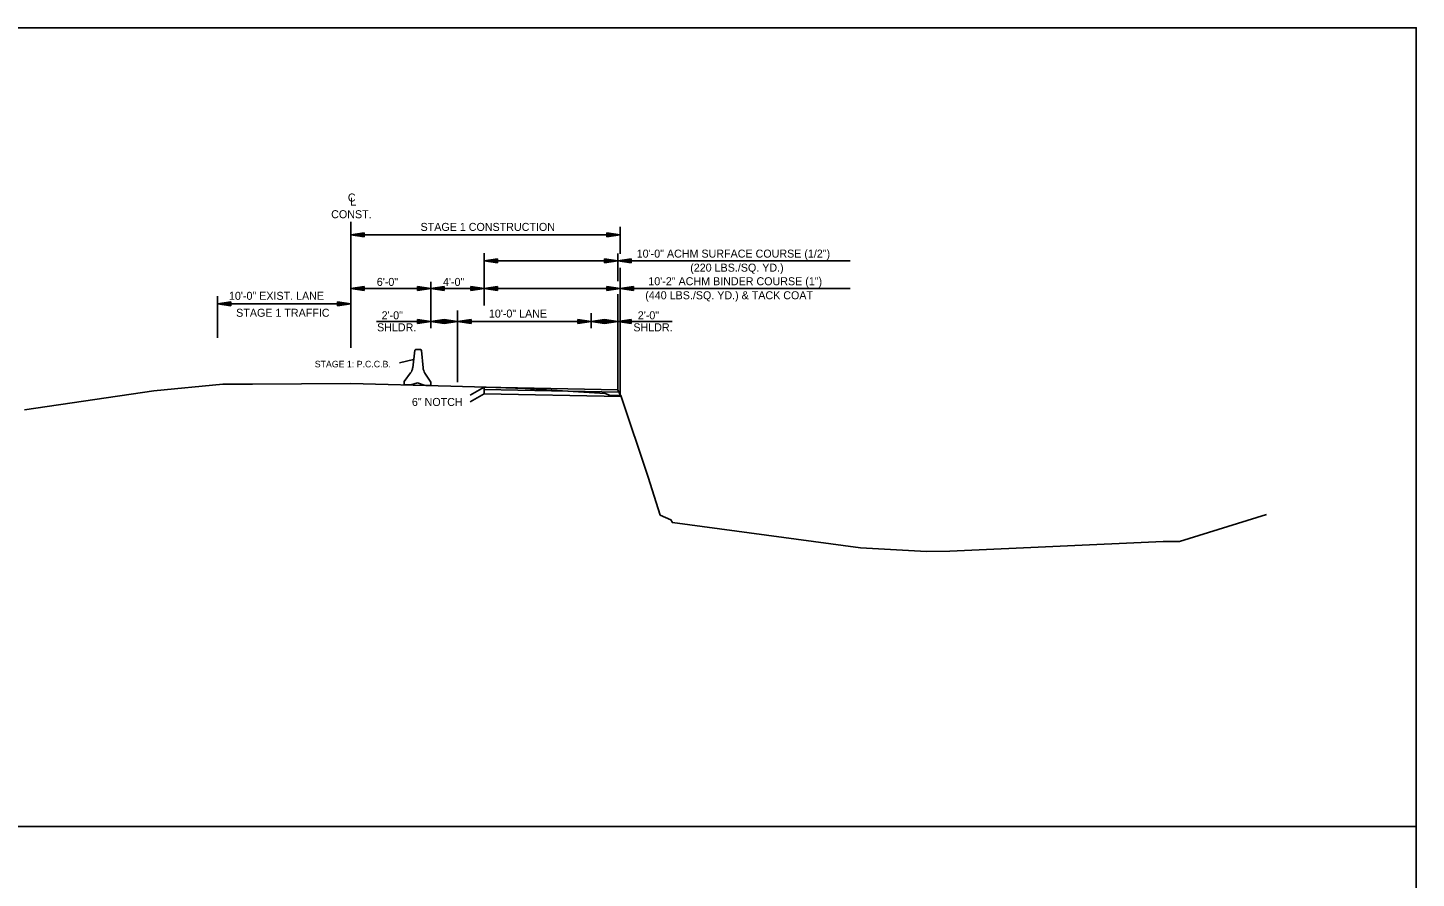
# Model space of a CAD drawing. Extents: x 2829243 to 2838161, y 467639 to 474695.
# Drawn here: x 2830081 to 2831122, y 469629 to 470266 of the extents above; entities that cross this region are included whole.
import ezdxf

# ---------------------------------------------------------------- set-up
doc = ezdxf.new("R2010")
doc.units = 0
for name, color, linetype in [('Default', 7, 'Continuous'), ('R_Dimension', 7, 'Continuous'), ('R_Draft', 7, 'Continuous'), ('R_Exist Surface', 7, 'Continuous'), ('R_Fin Surface', 7, 'Continuous'), ('R_MOT', 7, 'Continuous')]:
    doc.layers.add(name, color=color, linetype=linetype)

msp = doc.modelspace()

# ---------------------------------------------------------------- linework, layer by layer
at = {"layer": 'Default'}
msp.add_line((2829486.2, 469667.7), (2831121.8, 469667.7), dxfattribs=at)
msp.add_lwpolyline([(2829486.2, 470265.9), (2831121.8, 470265.9), (2831121.8, 468471.1), (2829486.2, 468471.1)], close=True, dxfattribs=at)
at = {"layer": 'R_Dimension'}
for p, q in [((2830323.3, 470026.2), (2830323.3, 470120.7)), ((2830333.3, 470112.3), (2830323.3, 470110.8)), ((2830323.3, 470110.8), (2830525.1, 470110.8)), ((2830333.3, 470109.3), (2830323.3, 470110.8)), ((2830333.3, 470112), (2830325, 470110.8)), ((2830333.3, 470109.5), (2830325, 470110.8)), ((2830333.3, 470111.8), (2830326.7, 470110.8)), ((2830333.3, 470109.8), (2830326.7, 470110.8)), ((2830333.3, 470111.5), (2830328.4, 470110.8)), ((2830333.3, 470110), (2830328.4, 470110.8)), ((2830333.3, 470111.3), (2830330.1, 470110.8)), ((2830333.3, 470110.3), (2830330.1, 470110.8)), ((2830333.3, 470111), (2830331.8, 470110.8)), ((2830333.3, 470110.5), (2830331.8, 470110.8)), ((2830333.3, 470109.3), (2830333.3, 470112.3)), ((2830515.1, 470112.3), (2830525.1, 470110.8)), ((2830515.1, 470109.3), (2830515.1, 470112.3)), ((2830515.1, 470112), (2830523.4, 470110.8)), ((2830515.1, 470111.8), (2830521.7, 470110.8)), ((2830515.1, 470111.5), (2830520, 470110.8)), ((2830515.1, 470111.3), (2830518.3, 470110.8)), ((2830515.1, 470111), (2830516.6, 470110.8)), ((2830515.1, 470109.3), (2830525.1, 470110.8)), ((2830515.1, 470110.3), (2830518.3, 470110.8)), ((2830515.1, 470109.8), (2830521.7, 470110.8)), ((2830515.1, 470109.5), (2830523.4, 470110.8)), ((2830515.1, 470110), (2830520, 470110.8)), ((2830515.1, 470110.5), (2830516.6, 470110.8)), ((2830525.1, 470096.6), (2830525.1, 470116.8)), ((2830423.3, 470058), (2830423.3, 470097.2)), ((2830433.3, 470092.9), (2830423.3, 470091.4)), ((2830423.3, 470091.4), (2830697.7, 470091.4)), ((2830433.3, 470089.9), (2830423.3, 470091.4)), ((2830433.3, 470092.6), (2830425, 470091.4)), ((2830433.3, 470090.1), (2830425, 470091.4)), ((2830433.3, 470092.4), (2830426.7, 470091.4)), ((2830433.3, 470090.4), (2830426.7, 470091.4)), ((2830433.3, 470092.1), (2830428.4, 470091.4)), ((2830433.3, 470090.6), (2830428.4, 470091.4)), ((2830433.3, 470091.9), (2830430.1, 470091.4)), ((2830433.3, 470090.9), (2830430.1, 470091.4)), ((2830433.3, 470091.6), (2830431.8, 470091.4)), ((2830433.3, 470091.1), (2830431.8, 470091.4)), ((2830433.3, 470089.9), (2830433.3, 470092.9)), ((2830513.4, 470092.9), (2830523.4, 470091.4)), ((2830513.4, 470089.9), (2830513.4, 470092.9)), ((2830513.4, 470092.6), (2830521.7, 470091.4)), ((2830513.4, 470092.4), (2830520, 470091.4)), ((2830513.4, 470092.1), (2830518.3, 470091.4)), ((2830513.4, 470091.9), (2830516.6, 470091.4)), ((2830513.4, 470091.6), (2830515, 470091.4)), ((2830513.4, 470089.9), (2830523.4, 470091.4)), ((2830513.4, 470090.9), (2830516.6, 470091.4)), ((2830513.4, 470090.4), (2830520, 470091.4)), ((2830513.4, 470090.1), (2830521.7, 470091.4)), ((2830513.4, 470090.6), (2830518.3, 470091.4)), ((2830513.4, 470091.1), (2830515, 470091.4)), ((2830523.4, 470076.2), (2830523.4, 470096.8)), ((2830533.4, 470092.9), (2830523.4, 470091.4)), ((2830533.4, 470089.9), (2830523.4, 470091.4)), ((2830533.4, 470092.6), (2830525.1, 470091.4)), ((2830533.4, 470090.1), (2830525.1, 470091.4)), ((2830533.4, 470092.4), (2830526.8, 470091.4)), ((2830533.4, 470090.4), (2830526.8, 470091.4)), ((2830533.4, 470092.1), (2830528.4, 470091.4)), ((2830533.4, 470090.6), (2830528.4, 470091.4)), ((2830533.4, 470091.9), (2830530.1, 470091.4)), ((2830533.4, 470090.9), (2830530.1, 470091.4)), ((2830533.4, 470091.6), (2830531.8, 470091.4)), ((2830533.4, 470091.1), (2830531.8, 470091.4)), ((2830533.4, 470089.9), (2830533.4, 470092.9)), ((2830525.1, 469991.5), (2830525.1, 470086.2)), ((2830333.3, 470072.2), (2830323.3, 470070.7)), ((2830343.3, 470070.7), (2830323.3, 470070.7)), ((2830333.3, 470069.2), (2830323.3, 470070.7)), ((2830333.3, 470071.9), (2830325, 470070.7)), ((2830333.3, 470069.4), (2830325, 470070.7)), ((2830333.3, 470071.7), (2830326.7, 470070.7)), ((2830333.3, 470069.7), (2830326.7, 470070.7)), ((2830333.3, 470071.4), (2830328.4, 470070.7)), ((2830333.3, 470069.9), (2830328.4, 470070.7)), ((2830333.3, 470071.2), (2830330.1, 470070.7)), ((2830333.3, 470070.2), (2830330.1, 470070.7)), ((2830333.3, 470070.9), (2830331.8, 470070.7)), ((2830333.3, 470070.4), (2830331.8, 470070.7)), ((2830333.3, 470069.2), (2830333.3, 470072.2)), ((2830383.3, 470070.7), (2830343.3, 470070.7)), ((2830373.3, 470072.2), (2830383.3, 470070.7)), ((2830373.3, 470069.2), (2830373.3, 470072.2)), ((2830373.3, 470071.9), (2830381.7, 470070.7)), ((2830373.3, 470071.7), (2830379.9, 470070.7)), ((2830373.3, 470071.4), (2830378.3, 470070.7)), ((2830373.3, 470071.2), (2830376.6, 470070.7)), ((2830373.3, 470070.9), (2830374.9, 470070.7)), ((2830373.3, 470069.2), (2830383.3, 470070.7)), ((2830373.3, 470070.2), (2830376.6, 470070.7)), ((2830373.3, 470069.7), (2830379.9, 470070.7)), ((2830373.3, 470069.4), (2830381.7, 470070.7)), ((2830373.3, 470069.9), (2830378.3, 470070.7)), ((2830373.3, 470070.4), (2830374.9, 470070.7)), ((2830383.3, 470052.1), (2830383.3, 470075.6)), ((2830393.3, 470072.2), (2830383.3, 470070.7)), ((2830423.3, 470070.7), (2830383.3, 470070.7)), ((2830393.3, 470069.2), (2830383.3, 470070.7)), ((2830393.3, 470071.9), (2830385, 470070.7)), ((2830393.3, 470069.4), (2830385, 470070.7)), ((2830393.3, 470071.7), (2830386.7, 470070.7)), ((2830393.3, 470069.7), (2830386.7, 470070.7)), ((2830393.3, 470071.4), (2830388.4, 470070.7)), ((2830393.3, 470069.9), (2830388.4, 470070.7)), ((2830393.3, 470071.2), (2830390.1, 470070.7)), ((2830393.3, 470070.2), (2830390.1, 470070.7)), ((2830393.3, 470070.9), (2830391.8, 470070.7)), ((2830393.3, 470070.4), (2830391.8, 470070.7)), ((2830393.3, 470069.2), (2830393.3, 470072.2)), ((2830413.3, 470072.2), (2830423.3, 470070.7)), ((2830413.3, 470069.2), (2830413.3, 470072.2)), ((2830413.3, 470071.9), (2830421.7, 470070.7)), ((2830413.3, 470071.7), (2830419.9, 470070.7)), ((2830413.3, 470071.4), (2830418.3, 470070.7)), ((2830413.3, 470071.2), (2830416.6, 470070.7)), ((2830413.3, 470070.9), (2830414.9, 470070.7)), ((2830413.3, 470069.2), (2830423.3, 470070.7)), ((2830413.3, 470070.2), (2830416.6, 470070.7)), ((2830413.3, 470069.7), (2830419.9, 470070.7)), ((2830413.3, 470069.4), (2830421.7, 470070.7)), ((2830413.3, 470069.9), (2830418.3, 470070.7)), ((2830413.3, 470070.4), (2830414.9, 470070.7)), ((2830433.3, 470072.2), (2830423.3, 470070.7)), ((2830423.3, 470070.7), (2830697.7, 470070.7)), ((2830433.3, 470069.2), (2830423.3, 470070.7)), ((2830433.3, 470071.9), (2830425, 470070.7)), ((2830433.3, 470069.4), (2830425, 470070.7)), ((2830433.3, 470071.7), (2830426.7, 470070.7)), ((2830433.3, 470069.7), (2830426.7, 470070.7)), ((2830433.3, 470071.4), (2830428.4, 470070.7)), ((2830433.3, 470069.9), (2830428.4, 470070.7)), ((2830433.3, 470071.2), (2830430.1, 470070.7)), ((2830433.3, 470070.2), (2830430.1, 470070.7)), ((2830433.3, 470070.9), (2830431.8, 470070.7)), ((2830433.3, 470070.4), (2830431.8, 470070.7)), ((2830433.3, 470069.2), (2830433.3, 470072.2)), ((2830515.1, 470072.2), (2830525.1, 470070.7)), ((2830515.1, 470069.2), (2830515.1, 470072.2)), ((2830515.1, 470071.9), (2830523.4, 470070.7)), ((2830515.1, 470071.7), (2830521.7, 470070.7)), ((2830515.1, 470071.4), (2830520, 470070.7)), ((2830515.1, 470071.2), (2830518.3, 470070.7)), ((2830515.1, 470070.9), (2830516.6, 470070.7)), ((2830515.1, 470069.2), (2830525.1, 470070.7)), ((2830515.1, 470070.2), (2830518.3, 470070.7)), ((2830515.1, 470069.7), (2830521.7, 470070.7)), ((2830515.1, 470069.4), (2830523.4, 470070.7)), ((2830515.1, 470069.9), (2830520, 470070.7)), ((2830515.1, 470070.4), (2830516.6, 470070.7)), ((2830535.1, 470072.2), (2830525.1, 470070.7)), ((2830535.1, 470069.2), (2830525.1, 470070.7)), ((2830535.1, 470071.9), (2830526.7, 470070.7)), ((2830535.1, 470069.4), (2830526.7, 470070.7)), ((2830535.1, 470071.7), (2830528.4, 470070.7)), ((2830535.1, 470069.7), (2830528.4, 470070.7)), ((2830535.1, 470071.4), (2830530.1, 470070.7)), ((2830535.1, 470069.9), (2830530.1, 470070.7)), ((2830535.1, 470071.2), (2830531.8, 470070.7)), ((2830535.1, 470070.2), (2830531.8, 470070.7)), ((2830535.1, 470070.9), (2830533.5, 470070.7)), ((2830535.1, 470070.4), (2830533.5, 470070.7)), ((2830535.1, 470069.2), (2830535.1, 470072.2)), ((2830223.3, 470033.7), (2830223.3, 470065)), ((2830233.3, 470060.7), (2830223.3, 470059.2)), ((2830323.3, 470059.2), (2830223.3, 470059.2)), ((2830233.3, 470057.7), (2830223.3, 470059.2)), ((2830233.3, 470060.5), (2830225, 470059.2)), ((2830233.3, 470058), (2830225, 470059.2)), ((2830233.3, 470060.2), (2830226.7, 470059.2)), ((2830233.3, 470058.2), (2830226.7, 470059.2)), ((2830233.3, 470060), (2830228.4, 470059.2)), ((2830233.3, 470058.5), (2830228.4, 470059.2)), ((2830233.3, 470059.7), (2830230.1, 470059.2)), ((2830233.3, 470058.7), (2830230.1, 470059.2)), ((2830233.3, 470059.4), (2830231.8, 470059.2)), ((2830233.3, 470059), (2830231.8, 470059.2)), ((2830233.3, 470057.7), (2830233.3, 470060.7)), ((2830313.3, 470060.7), (2830323.3, 470059.2)), ((2830313.3, 470057.7), (2830313.3, 470060.7)), ((2830313.3, 470060.5), (2830321.7, 470059.2)), ((2830313.3, 470060.2), (2830319.9, 470059.2)), ((2830313.3, 470060), (2830318.3, 470059.2)), ((2830313.3, 470059.7), (2830316.6, 470059.2)), ((2830313.3, 470059.4), (2830314.9, 470059.2)), ((2830313.3, 470057.7), (2830323.3, 470059.2)), ((2830313.3, 470058.7), (2830316.6, 470059.2)), ((2830313.3, 470058.2), (2830319.9, 470059.2)), ((2830313.3, 470058), (2830321.7, 470059.2)), ((2830313.3, 470058.5), (2830318.3, 470059.2)), ((2830313.3, 470059), (2830314.9, 470059.2)), ((2830523.4, 469994.8), (2830523.4, 470066.4)), ((2830373.4, 470047.4), (2830383.4, 470045.9)), ((2830373.4, 470044.4), (2830373.4, 470047.4)), ((2830383.4, 470041), (2830383.4, 470052.1)), ((2830393.4, 470047.4), (2830383.4, 470045.9)), ((2830393.4, 470047.4), (2830403.4, 470045.9)), ((2830393.4, 470044.4), (2830393.4, 470047.4)), ((2830393.4, 470044.4), (2830393.4, 470047.4)), ((2830403.4, 470000.6), (2830403.4, 470054.2)), ((2830413.4, 470047.4), (2830403.4, 470045.9)), ((2830413.4, 470044.4), (2830413.4, 470047.4)), ((2830493.4, 470047.4), (2830503.4, 470045.9)), ((2830493.4, 470044.4), (2830493.4, 470047.4)), ((2830503.4, 470041), (2830503.4, 470052.1)), ((2830513.4, 470047.4), (2830503.4, 470045.9)), ((2830513.4, 470044.4), (2830513.4, 470047.4)), ((2830513.4, 470047.4), (2830523.4, 470045.9)), ((2830513.4, 470044.4), (2830513.4, 470047.4)), ((2830523.4, 470041), (2830523.4, 470052.1)), ((2830533.4, 470047.4), (2830523.4, 470045.9)), ((2830533.4, 470044.4), (2830533.4, 470047.4)), ((2830403.4, 470045.9), (2830342.6, 470045.9)), ((2830373.4, 470047.2), (2830381.7, 470045.9)), ((2830373.4, 470046.9), (2830380, 470045.9)), ((2830373.4, 470046.7), (2830378.3, 470045.9)), ((2830373.4, 470046.4), (2830376.6, 470045.9)), ((2830373.4, 470046.2), (2830375, 470045.9)), ((2830373.4, 470044.4), (2830383.4, 470045.9)), ((2830373.4, 470045.4), (2830376.6, 470045.9)), ((2830373.4, 470044.9), (2830380, 470045.9)), ((2830373.4, 470044.7), (2830381.7, 470045.9)), ((2830373.4, 470045.2), (2830378.3, 470045.9)), ((2830373.4, 470045.7), (2830375, 470045.9)), ((2830393.4, 470044.4), (2830383.4, 470045.9)), ((2830393.4, 470047.2), (2830385.1, 470045.9)), ((2830393.4, 470044.7), (2830385.1, 470045.9)), ((2830393.4, 470046.9), (2830386.8, 470045.9)), ((2830393.4, 470044.9), (2830386.8, 470045.9)), ((2830393.4, 470046.7), (2830388.4, 470045.9)), ((2830393.4, 470045.2), (2830388.4, 470045.9)), ((2830393.4, 470046.4), (2830390.1, 470045.9)), ((2830393.4, 470045.4), (2830390.1, 470045.9)), ((2830393.4, 470046.2), (2830391.8, 470045.9)), ((2830393.4, 470045.7), (2830391.8, 470045.9)), ((2830393.4, 470047.2), (2830401.7, 470045.9)), ((2830393.4, 470046.9), (2830400, 470045.9)), ((2830393.4, 470046.7), (2830398.3, 470045.9)), ((2830393.4, 470046.4), (2830396.6, 470045.9)), ((2830393.4, 470046.2), (2830395, 470045.9)), ((2830393.4, 470044.4), (2830403.4, 470045.9)), ((2830393.4, 470045.4), (2830396.6, 470045.9)), ((2830393.4, 470044.9), (2830400, 470045.9)), ((2830393.4, 470044.7), (2830401.7, 470045.9)), ((2830393.4, 470045.2), (2830398.3, 470045.9)), ((2830393.4, 470045.7), (2830395, 470045.9)), ((2830503.4, 470045.9), (2830403.4, 470045.9)), ((2830413.4, 470044.4), (2830403.4, 470045.9)), ((2830413.4, 470047.2), (2830405.1, 470045.9)), ((2830413.4, 470044.7), (2830405.1, 470045.9)), ((2830413.4, 470046.9), (2830406.8, 470045.9)), ((2830413.4, 470044.9), (2830406.8, 470045.9)), ((2830413.4, 470046.7), (2830408.4, 470045.9)), ((2830413.4, 470045.2), (2830408.4, 470045.9)), ((2830413.4, 470046.4), (2830410.1, 470045.9)), ((2830413.4, 470045.4), (2830410.1, 470045.9)), ((2830413.4, 470046.2), (2830411.8, 470045.9)), ((2830413.4, 470045.7), (2830411.8, 470045.9)), ((2830493.4, 470047.2), (2830501.7, 470045.9)), ((2830493.4, 470046.9), (2830500, 470045.9)), ((2830493.4, 470046.7), (2830498.3, 470045.9)), ((2830493.4, 470046.4), (2830496.6, 470045.9)), ((2830493.4, 470046.2), (2830495, 470045.9)), ((2830493.4, 470044.4), (2830503.4, 470045.9)), ((2830493.4, 470045.4), (2830496.6, 470045.9)), ((2830493.4, 470044.9), (2830500, 470045.9)), ((2830493.4, 470044.7), (2830501.7, 470045.9)), ((2830493.4, 470045.2), (2830498.3, 470045.9)), ((2830493.4, 470045.7), (2830495, 470045.9)), ((2830503.4, 470045.9), (2830564.1, 470045.9)), ((2830513.4, 470044.4), (2830503.4, 470045.9)), ((2830513.4, 470047.2), (2830505.1, 470045.9)), ((2830513.4, 470044.7), (2830505.1, 470045.9)), ((2830513.4, 470046.9), (2830506.8, 470045.9)), ((2830513.4, 470044.9), (2830506.8, 470045.9)), ((2830513.4, 470046.7), (2830508.4, 470045.9)), ((2830513.4, 470045.2), (2830508.4, 470045.9)), ((2830513.4, 470046.4), (2830510.1, 470045.9)), ((2830513.4, 470045.4), (2830510.1, 470045.9)), ((2830513.4, 470046.2), (2830511.8, 470045.9)), ((2830513.4, 470045.7), (2830511.8, 470045.9)), ((2830513.4, 470047.2), (2830521.7, 470045.9)), ((2830513.4, 470046.9), (2830520, 470045.9)), ((2830513.4, 470046.7), (2830518.3, 470045.9)), ((2830513.4, 470046.4), (2830516.6, 470045.9)), ((2830513.4, 470046.2), (2830515, 470045.9)), ((2830513.4, 470044.4), (2830523.4, 470045.9)), ((2830513.4, 470045.4), (2830516.6, 470045.9)), ((2830513.4, 470044.9), (2830520, 470045.9)), ((2830513.4, 470044.7), (2830521.7, 470045.9)), ((2830513.4, 470045.2), (2830518.3, 470045.9)), ((2830513.4, 470045.7), (2830515, 470045.9)), ((2830533.4, 470044.4), (2830523.4, 470045.9)), ((2830533.4, 470047.2), (2830525.1, 470045.9)), ((2830533.4, 470044.7), (2830525.1, 470045.9)), ((2830533.4, 470046.9), (2830526.8, 470045.9)), ((2830533.4, 470044.9), (2830526.8, 470045.9)), ((2830533.4, 470046.7), (2830528.4, 470045.9)), ((2830533.4, 470045.2), (2830528.4, 470045.9)), ((2830533.4, 470046.4), (2830530.1, 470045.9)), ((2830533.4, 470045.4), (2830530.1, 470045.9)), ((2830533.4, 470046.2), (2830531.8, 470045.9)), ((2830533.4, 470045.7), (2830531.8, 470045.9)), ((2830359.7, 470015.1), (2830370.4, 470017.6)), ((2830523.4, 469994.8), (2830423.3, 469996.8)), ((2830423.3, 469996.8), (2830423.3, 469996.8)), ((2830423.3, 469996.8), (2830423.3, 469996.8)), ((2830423.3, 469996.8), (2830423.3, 469996.8)), ((2830423.3, 469996.8), (2830423.3, 469995.1)), ((2830423.3, 469995.1), (2830423.3, 469995.1)), ((2830423.3, 469995.1), (2830524.2, 469993.1)), ((2830524.2, 469993.1), (2830423.3, 469995.1)), ((2830423.3, 469995.1), (2830423.3, 469995.1)), ((2830423.3, 469995.1), (2830423.3, 469995.1)), ((2830423.3, 469995.1), (2830423.3, 469995.1)), ((2830423.3, 469995.1), (2830423.3, 469991.8)), ((2830423.3, 469991.8), (2830423.3, 469991.8)), ((2830423.3, 469991.8), (2830525.9, 469989.9)), ((2830523.4, 469994.8), (2830523.4, 469994.8)), ((2830524.2, 469993.1), (2830523.4, 469994.8)), ((2830523.4, 469994.8), (2830523.4, 469994.8)), ((2830525.9, 469989.9), (2830524.2, 469993.1)), ((2830524.2, 469993.1), (2830524.2, 469993.1)), ((2830524.2, 469993.1), (2830524.2, 469993.1))]:
    msp.add_line(p, q, dxfattribs=at)
at = {"layer": 'R_Draft'}
for p, q in [((2830423.3, 469996.8), (2830412.8, 469990.7)), ((2830423.3, 469991.8), (2830412.8, 469985.7))]:
    msp.add_line(p, q, dxfattribs=at)
at = {"layer": 'R_Exist Surface'}
msp.add_lwpolyline([(2830078.8, 469979.8), (2830175.8, 469994.1), (2830227.3, 469999.1), (2830249.6, 469999.1), (2830323.1, 469999.6), (2830398.4, 469997.5), (2830424.8, 469996.7), (2830454.1, 469995.7), (2830514, 469992.1), (2830517.3, 469990.7), (2830525.7, 469990.6), (2830546.2, 469929.3), (2830555.3, 469901), (2830563.2, 469897.4), (2830564.4, 469895.4), (2830705.3, 469876.5), (2830754.8, 469873.8), (2830772.3, 469873.9), (2830932.1, 469881.3), (2830944.5, 469881.1), (2831009.6, 469901.4)], dxfattribs=at)
at = {"layer": 'R_Fin Surface'}
for p, q in [((2830423.3, 469996.8), (2830523.4, 469994.8)), ((2830523.4, 469994.8), (2830525.9, 469989.9))]:
    msp.add_line(p, q, dxfattribs=at)
at = {"layer": 'R_MOT'}
for p, q in [((2830371.3, 470024.4), (2830369.7, 470011.3)), ((2830371.3, 470024.4), (2830372, 470025)), ((2830372, 470025), (2830375.7, 470024.9)), ((2830375.7, 470024.9), (2830376.4, 470024.3)), ((2830376.4, 470024.3), (2830377.5, 470011.2)), ((2830368.1, 470007.4), (2830363.4, 470001)), ((2830378.9, 470007.2), (2830383.4, 470000.6)), ((2830363.4, 470001), (2830363.3, 469998.5)), ((2830368.3, 469998.4), (2830363.3, 469998.5)), ((2830368.3, 469998.4), (2830373.4, 469999.9)), ((2830373.4, 469999.9), (2830378.3, 469998.2)), ((2830378.3, 469998.2), (2830383.3, 469998.1)), ((2830383.4, 470000.6), (2830383.3, 469998.1))]:
    msp.add_line(p, q, dxfattribs=at)
for centre, start, end in [((2830361.4, 470012.4), 323.8622, 352.8452), ((2830385.8, 470011.9), 184.8632, 213.8462)]:
    msp.add_arc(centre, 8.33, start, end, dxfattribs=at)

# ---------------------------------------------------------------- texts
at = {"layer": 'R_Dimension'}
for s, p in [('C', (2830321.1, 470135.8)), ('L', (2830322.9, 470132.7)), ('CONST.', (2830308.6, 470123.3)), ('STAGE 1 CONSTRUCTION', (2830375.6, 470113.8)), ('10\'-0" ACHM SURFACE COURSE (1/2")', (2830537.6, 470093.8)), ('(220 LBS./SQ. YD.)', (2830577.7, 470083.3)), ('6\'-0"', (2830342.8, 470072.6)), ('4\'-0"', (2830392.4, 470072.6)), ('10\'-2" ACHM BINDER COURSE (1")', (2830546.3, 470073.1)), ('10\'-0" EXIST. LANE', (2830232, 470062.2)), ('(440 LBS./SQ. YD.) & TACK COAT', (2830544, 470062.6)), ('STAGE 1 TRAFFIC', (2830237.4, 470049.5)), ('2\'-0"', (2830346.4, 470047.6)), ('10\'-0" LANE', (2830426.8, 470048.9)), ('2\'-0"', (2830538.4, 470047.6)), ('SHLDR.', (2830343, 470038.6)), ('SHLDR.', (2830535.1, 470038.6)), ('6" NOTCH', (2830369.1, 469982.7))]:
    msp.add_text(s, height=6, dxfattribs=at).set_placement(p)
at = {"layer": 'R_Draft'}
msp.add_text('STAGE 1: P.C.C.B.', height=4.918, dxfattribs=at).set_placement((2830296.3, 470011.6))
at = {"layer": 'R_MOT'}
msp.add_text('DWB 1-14-10', height=0.04, rotation=88.8542, dxfattribs=at).set_placement((2830363.4, 469998.5))

doc.saveas('drawing.dxf')
